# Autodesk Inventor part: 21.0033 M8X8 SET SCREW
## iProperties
Created: 2012-10
Part Number: 21.0033 M8X8 SET SCREW
Document SubType Name: Modeling
Designer: Administrator
Density: 7.85 g/cm^3
Material: Steel
Mass: 1.89077 g
Surface Area: 3.03432 cm^2
Volume: 0.240862 cm^3
Author: Administrator
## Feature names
1. Base1
